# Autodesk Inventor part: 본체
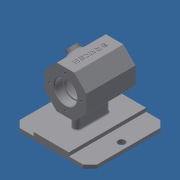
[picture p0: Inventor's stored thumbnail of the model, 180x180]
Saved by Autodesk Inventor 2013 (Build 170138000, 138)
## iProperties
Created: 2018-06
Part Number: 본체
Material: Generic
Document SubType Name: Modeling
Designer: Administrator
Density: 1 g/cm^3
Author: Administrator
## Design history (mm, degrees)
sketch "스케치1"
  geometry: L1 (-12.426, 30)-(12.426, 30); L2 (12.426, 30)-(30, 12.426); L3 (30, 12.426)-(30, -12.426); L4 (30, -12.426)-(12.426, -30); L5 (12.426, -30)-(-12.426, -30); L6 (-12.426, -30)-(-30, -12.426); L7 (-30, -12.426)-(-30, 12.426); L8 (-30, 12.426)-(-12.426, 30); L9 (-12.426, 30)-(0, 0); L10 (0, 0)-(12.426, 30); L11 (-5, -30)-(-5, -52); L12 (-5, -52)-(-25, -52); L13 (-25, -52)-(-25, -57); L14 (-25, -57)-(-55, -57); L15 (-55, -62)-(55, -62); L16 (55, -62)-(55, -57); L17 (55, -57)-(25, -57); L18 (25, -57)-(25, -52); L19 (25, -52)-(5, -52); L20 (5, -52)-(5, -30); L21 (-55, -62)-(-55, -57); L22 (-5, -52)-(5, -52); C1 r 30 at (0, 0); 5 further points
  constraints: 44 end point, 9 parallel, 6 equal length, 4 midpoint, 4 tangent, 4 vertical alignment, 3 horizontal alignment, 3 perpendicular, 2 horizontal, 2 point on line, 2 vertical, 1 centre point, 1 coincident
  dimensions: "d0" = 60 diameter of C1; "d2" = 110 distance of L15.start L15.end; "d4" = 10 distance between parallel lines of L15 L19; "d5" = 5 distance of L15.end L16.end; "d6" = 62 distance from line of L15 point (0, 0); "d7" = 30 distance of L13.end L14.end; "d8" = 10 distance between parallel lines of L20 L11
extrude "돌출1" new body sketch "스케치1" stored distance "d9" = 70; taper "d10" = 0 deg
extrude "돌출2" join sketch "스케치1" stored distance "d11" = 48; taper "d12" = 0 deg
extrude "돌출3" join sketch "스케치1" stored distance "d13" = 110; taper "d14" = 0 deg
sketch "스케치2"
  geometry: L1 (12.426, 35)-(-12.426, 35) reference; L2 (0, 35)-(0, -35); L3 (-12.426, -35)-(12.426, -35) reference; L4 (0, 35)-(16, 35); L5 (30, 35)-(12.426, 35) reference; L6 (16, 35)-(16, 23); L7 (16, 23)-(14, 23); L8 (14, 23)-(14, 20); L9 (14, 20)-(25, 20); L10 (25, 20)-(25, -20); L11 (25, -20)-(14, -20); L12 (14, -20)-(14, -23); L13 (14, -23)-(16, -23); L14 (16, -23)-(16, -35); L15 (12.426, -35)-(30, -35) reference; 1 further point
  constraints: 22 end point, 4 parallel, 3 collinear, 3 vertical alignment, 2 midpoint, 2 perpendicular, 2 point on line, 1 horizontal
  dimensions: "d15" = 12 distance of L4.end L6.end; "d17" = 40 distance of L9.end L10.end; "d18" = 32 diameter of L6 L2; "d19" = 28 diameter of L8 L2; "d20" = 50 diameter of L10 L2
revolve "회전1" sketch "스케치2" stored, may be unused: angle "d21" = 90 deg
sketch "스케치3"
  geometry: C1 r 16 at (0, 0) reference; 1 further point
  constraints: 1 vertical alignment
  dimensions: "d22" = 23 distance of C1.centre point (0, 23)
hole "구멍1" sketch "스케치3" at (0, 23) diameter "d23" = 3.242; stored, may be unused: countersink angle "d27" = 90 deg, drill point angle "d29" = 118 deg; dims "d24" = 8, "d25" = 4, "d26" = 2, "d28" = 10
hole "구멍2" diameter "d35" = 10; stored, may be unused: countersink angle "d39" = 90 deg, drill point angle "d41" = 118 deg; dims "d33" = 55, "d34" = 10, "d36" = 8, "d37" = 4, "d38" = 2, "d40" = 10
fillet "모깎기1" dims "d42" = 3
fillet "모깎기2" dims "d43" = 0.3
node "작업 평면1"
sketch "스케치4"
  geometry: C1 r 8 at (-12.426, 35); 1 further point
  constraints: 1 centre point, 1 coincident
  dimensions: "d45" = 16 diameter of C1
extrude "돌출4" join sketch "스케치4" stored distance "d47" = 110; taper "d48" = 0 deg
hole "구멍3" diameter "d51" = 8; stored, may be unused: countersink angle "d55" = 90 deg, drill point angle "d57" = 118 deg; dims "d49" = 10, "d50" = 10, "d52" = 8, "d53" = 4, "d54" = 2, "d56" = 10
sketch "스케치5"
  geometry: L1 (0, 70)-(24.853, 70) reference; L2 (42.426, 70)-(42.426, 0) reference; 2 further points
  constraints: 1 other
  dimensions: "d58" = 35 distance from line of point (12.426, 35) L1; "d59" = 30 distance from line of point (12.426, 35) L2
feature "엠보싱1" sketch "스케치5" dims "d0" = 60, "d2" = 110, "d4" = 10, "d5" = 5, "d6" = 62, "d7" = 30, "d8" = 10, "d60" = 0.5, "d61" = 0
chamfer "모따기1" distance "d62" = 10; stored, may be unused: second distance "d63" = 2, angle "d64" = 45 deg
fillet "모깎기3" dims "d65" = 5
fillet "모깎기4" dims "d66" = 2
fillet "모깎기5" dims "d67" = 3
chamfer "모따기2" distance "d68" = 1; stored, may be unused: second distance "d69" = 2, angle "d70" = 45 deg
fillet "모깎기6" dims "d71" = 1
chamfer "모따기3" distance "d72" = 1; stored, may be unused: second distance "d73" = 2, angle "d74" = 45 deg
node "솔리드1"
pattern_circular "원형 패턴1" dims angle "d31" = 360 deg
mirror "대칭1"
mirror "대칭2"
other parameters: "d44" = 7
